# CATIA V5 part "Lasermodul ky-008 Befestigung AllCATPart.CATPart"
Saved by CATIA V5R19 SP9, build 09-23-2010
Part number: Lasermodul Befestigung_AllCATPart
Bounding box of the stored display mesh (mm): x -56.666 to 76.458, y -48.802 to 51.689, z -7 to 30
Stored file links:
  D:\Temporäre Sachen\Lasermodul KY-008 with mounting for adjustment\Lasermodul Befestigung_AllCATPart.CATPart
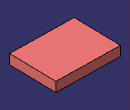
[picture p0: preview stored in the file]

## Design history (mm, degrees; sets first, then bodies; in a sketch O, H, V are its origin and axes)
Body1 (main body)
Body2 "KY-008 Laser Modul .1\\KY-008 Laser Modul.1\\Hauptkörper"
  Solid1: solid without history
Body3 "KY-008 Laser Modul .1\\Stiftleiste gewinkelt.1\\Hauptkörper"
  Solid2 "Volumen.1": solid without history
Body4 "KY-008 Laser Modul .1\\Part1.1\\Hauptkörper"
  Solid3 "Volumen.1": solid without history
Body5 "Halter Lasermodul\\Hauptkörper"
  Solid4 "Volumen.1": solid without history
Body6 "Part1.2\\Hauptkörper"
  Solid5 "Volumen.1": solid without history
Body7 "Mutter M3.1\\Hauptkörper"
  Solid6 "Volumen.1": solid without history
Body8 "Stecker 3fach.1\\Carrera Breadboard 05_Components_K3_1"
  Solid7 "Volumen.1": solid without history
Body9 "Stecker 3fach.1\\Carrera Breadboard 05_Components_K3_2"
  Solid8 "Volumen.1": solid without history
Body10 "Stecker 3fach.1\\Carrera Breadboard 05_Components_K3_3"
  Solid9 "Volumen.1": solid without history
Body11 "Stecker 3fach.1\\Carrera Breadboard 05_Components_K3_4"
  Solid10 "Volumen.1": solid without history
Body12 "Stecker 3fach.1\\Carrera Breadboard 05_Components_K3_8"
  Solid11 "Volumen.1": solid without history
Body13 "Stecker 3fach.1\\Carrera Breadboard 05_Components_K3_9"
  Solid12 "Volumen.1": solid without history
Body14 "Stecker 3fach.1\\Carrera Breadboard 05_Components_K3_10"
  Solid13 "Volumen.1": solid without history
Body15 "Befestigungsplatte\\Hauptkörper"
  Solid14 "Volumen.1": solid without history
Body16 "Schraube M3x12.1\\Hauptkörper"
  Solid15 "Volumen.1": solid without history
Body17 "Schraube M3x12.2\\Hauptkörper"
  Solid16 "Volumen.1": solid without history
Body18 "Schraube M3x12.3\\Hauptkörper"
  Solid17 "Volumen.1": solid without history
Body19 "Distanz\\Hauptkörper"
  Solid18 "Volumen.1": solid without history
